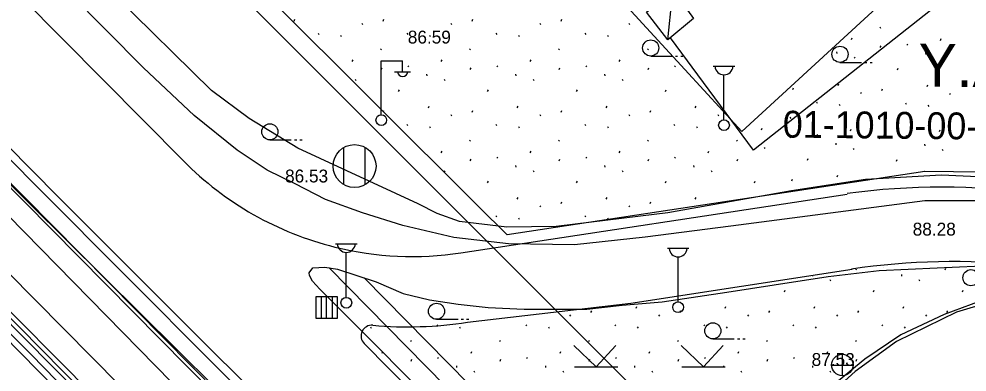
# Model space of a CAD drawing. Extents: x 412225 to 413380, y 4456471 to 4457189.
# Drawn here: x 412532.8 to 412621.2, y 4456847.1 to 4456880 of the extents above; entities that cross this region are included whole.
import ezdxf

# ---------------------------------------------------------------- set-up
doc = ezdxf.new("R2010")
doc.units = 0
for name, color, linetype in [('0_HALİHAZIR', 7, 'Continuous'), ('0_KADASTRO', 7, 'Continuous'), ('Level 27', 7, 'Continuous'), ('Level 28', 7, 'Continuous'), ('Level 41', 7, 'Continuous'), ('Level 56', 7, 'Continuous'), ('Level 57', 7, 'Continuous'), ('Level 62', 7, 'Continuous'), ('Level 8', 7, 'Continuous')]:
    doc.layers.add(name, color=color, linetype=linetype)

msp = doc.modelspace()

# ---------------------------------------------------------------- linework, layer by layer
at = {"layer": '0_HALİHAZIR'}
for p, q in [((412593.314, 4456878.021), (412593.767, 4456882.742)), ((412566.588, 4456871.077), (412566.588, 4456876.077)), ((412566.588, 4456876.077), (412568.588, 4456876.077)), ((412568.588, 4456875.077), (412568.588, 4456876.077)), ((412591.707, 4456876.524), (412593.707, 4456876.524)), ((412594.007, 4456876.524), (412594.207, 4456876.524)), ((412594.507, 4456876.524), (412594.707, 4456876.524)), ((412609.348, 4456875.935), (412611.348, 4456875.934)), ((412611.648, 4456875.934), (412611.848, 4456875.934)), ((412612.148, 4456875.934), (412612.348, 4456875.934)), ((412567.828, 4456875.037), (412569.328, 4456875.037)), ((412597.537, 4456875.58), (412599.537, 4456875.58)), ((412598.537, 4456870.58), (412598.537, 4456874.773)), ((412556.214, 4456868.712), (412558.214, 4456868.712)), ((412558.514, 4456868.712), (412558.714, 4456868.712)), ((412559.014, 4456868.712), (412559.214, 4456868.712)), ((412563.107, 4456864.536), (412563.107, 4456867.996)), ((412565.107, 4456864.536), (412565.107, 4456867.996)), ((412562.339, 4456859.028), (412564.339, 4456859.028)), ((412593.262, 4456858.61), (412595.262, 4456858.61)), ((412563.339, 4456854.028), (412563.339, 4456858.221)), ((412594.262, 4456853.61), (412594.262, 4456857.803)), ((412562.506, 4456854.084), (412560.506, 4456854.084)), ((412560.506, 4456854.084), (412560.506, 4456852.084)), ((412562.506, 4456854.084), (412560.506, 4456854.084)), ((412560.506, 4456854.084), (412560.506, 4456852.084)), ((412561.011, 4456852.084), (412561.011, 4456854.084)), ((412561.506, 4456852.084), (412561.506, 4456854.084)), ((412562.054, 4456852.084), (412562.054, 4456854.084)), ((412562.506, 4456852.084), (412562.506, 4456854.084)), ((412562.506, 4456852.084), (412562.506, 4456854.084)), ((412560.506, 4456852.084), (412562.506, 4456852.084)), ((412560.506, 4456852.084), (412562.506, 4456852.084)), ((412571.748, 4456851.983), (412573.748, 4456851.983)), ((412574.048, 4456851.983), (412574.248, 4456851.983)), ((412574.548, 4456851.983), (412574.748, 4456851.983)), ((412586.614, 4456847.539), (412584.554, 4456849.529)), ((412586.614, 4456847.539), (412588.464, 4456849.549)), ((412596.614, 4456847.538), (412594.554, 4456849.529)), ((412596.614, 4456847.538), (412598.464, 4456849.548)), ((412597.498, 4456850.158), (412599.498, 4456850.158)), ((412599.798, 4456850.158), (412599.998, 4456850.158)), ((412600.298, 4456850.158), (412600.498, 4456850.158)), ((412609.578, 4456846.717), (412609.578, 4456848.717)), ((412608.558, 4456847.707), (412610.558, 4456847.707)), ((412584.594, 4456847.539), (412588.634, 4456847.539)), ((412594.594, 4456847.539), (412598.634, 4456847.538))]:
    msp.add_line(p, q, dxfattribs=at)
for points in [[(412644.931, 4456753.555), (412630.555, 4456767.782), (412604.684, 4456793.709), (412582.154, 4456816.287), (412559.135, 4456839.628), (412534.75, 4456864.124), (412499.888, 4456899.345), (412487.433, 4456911.736), (412459.99, 4456939.333), (412440.337, 4456959.115), (412419.902, 4456979.921), (412392.691, 4457007.039), (412362.588, 4457037.58), (412334.209, 4457066.321), (412297.701, 4457103.437), (412284.18, 4457117.149)], [(412284.17, 4457116.265), (412296.803, 4457102.771), (412316.426, 4457082.291), (412338.061, 4457060.18), (412363.233, 4457034.899), (412383.867, 4457014.022), (412425.083, 4456972.499), (412446.131, 4456951.075), (412463.226, 4456933.647), (412501.75, 4456894.857), (412523.558, 4456872.918), (412554.446, 4456842.344)], [(412283.985, 4457100.322), (412303.353, 4457080.961), (412332.911, 4457051.149), (412362.488, 4457021.336), (412400.253, 4456983.455), (412425.306, 4456957.949), (412451.956, 4456931.175), (412483.613, 4456899.459), (412507.045, 4456875.463), (412533.953, 4456848.693), (412570.746, 4456810.938), (412594.382, 4456786.967), (412618.72, 4456762.275), (412633.267, 4456747.178), (412636.335, 4456744.215)], [(412645.421, 4456754.062), (412629.127, 4456770.178), (412599.147, 4456800.409), (412567.615, 4456832.31), (412536.489, 4456863.396), (412502.72, 4456897.599), (412471.675, 4456928.735), (412445.148, 4456955.565), (412406.259, 4456994.837)], [(412637.165, 4456746.318), (412618.159, 4456765.78), (412589.798, 4456794.375), (412560.702, 4456823.748), (412525.834, 4456858.92), (412495.532, 4456889.87), (412469.975, 4456915.531), (412420.275, 4456965.756), (412393.731, 4456992.619)], [(412414.019, 4456980.608), (412430.818, 4456963.728), (412462.102, 4456931.987), (412481.52, 4456912.466), (412499.923, 4456893.817), (412530.253, 4456863.229), (412548.59, 4456844.546), (412567.492, 4456825.478), (412597.357, 4456795.212), (412619.629, 4456772.724)], [(412412.412, 4456976.824), (412430.58, 4456958.484), (412471.136, 4456917.576), (412494.611, 4456893.791), (412529.094, 4456859.09), (412552.718, 4456835.192), (412591.392, 4456796.015), (412615.481, 4456771.779), (412632.916, 4456754.119)], [(412635.095, 4456744.706), (412621.293, 4456758.968), (412594.514, 4456786.189), (412564.28, 4456816.959), (412527.989, 4456853.886), (412497.963, 4456883.985), (412468.818, 4456913.357), (412423.738, 4456958.933), (412408.728, 4456974.086)], [(412637.945, 4456899.275), (412621.744, 4456883.95), (412601.277, 4456867.764)], [(412635.655, 4456863.173), (412632.712, 4456864.33), (412628.216, 4456864.971), (412618.808, 4456865.408), (412611.713, 4456865.008), (412604.825, 4456863.97), (412593.317, 4456861.895), (412589.231, 4456861.424), (412582.882, 4456860.625), (412578.297, 4456860.557), (412573.901, 4456861.085), (412571.802, 4456861.843), (412570.047, 4456862.738), (412558.81, 4456867.948), (412554.283, 4456870.692), (412550.76, 4456873.32), (412541.737, 4456882.227), (412530.428, 4456894.636)], [(412623.327, 4456863.035), (412617.262, 4456863.012), (412609.896, 4456862.049), (412599.167, 4456860.676), (412591.194, 4456859.655), (412584.597, 4456858.934), (412578.465, 4456859.008), (412573.344, 4456859.624), (412568.611, 4456860.738), (412564.846, 4456861.915), (412561.409, 4456863.163), (412558.561, 4456864.601), (412555.978, 4456865.878), (412553.156, 4456867.743), (412549.147, 4456870.988), (412544.431, 4456875.423), (412537.507, 4456882.438), (412529.679, 4456890.558)], [(412601.277, 4456867.764), (412593.565, 4456878.231)], [(412574.046, 4456841.577), (412560.867, 4456854.796), (412560.182, 4456855.542), (412559.895, 4456856.064), (412559.891, 4456856.327), (412560.23, 4456856.792), (412561.346, 4456856.858), (412562.516, 4456856.661), (412566.117, 4456855.465), (412568.631, 4456854.384), (412571.105, 4456853.812), (412573.757, 4456853.407), (412576.556, 4456853.086), (412579.928, 4456852.939), (412582.936, 4456852.933), (412585.763, 4456852.942), (412589.045, 4456853.286), (412592.771, 4456853.603), (412598.79, 4456854.513), (412603.218, 4456855.186), (412608.253, 4456855.967), (412612.995, 4456856.546), (412618.415, 4456856.79), (412623.951, 4456857.035)], [(412597.174, 4456820.503), (412576.231, 4456842.04), (412561.741, 4456856.791)], [(412565.002, 4456855.835), (412578.684, 4456841.949), (412597.738, 4456822.746)], [(412652.353, 4456846.965), (412647.413, 4456849.769), (412643.247, 4456851.45), (412638.775, 4456852.65), (412633.482, 4456853.773), (412630.335, 4456854.302), (412627.786, 4456854.429), (412625.207, 4456854.276), (412622.405, 4456853.676), (412619.054, 4456852.427), (412615.022, 4456850.527), (412611.653, 4456848.275), (412608.162, 4456845.364)]]:
    msp.add_lwpolyline(points, dxfattribs=at)
msp.add_lwpolyline([(412593.314, 4456878.021), (412591.319, 4456880.602), (412593.767, 4456882.742), (412595.699, 4456880.014)], close=True, dxfattribs=at)
for centre, radius in [((412591.707, 4456877.274), 0.75), ((412609.348, 4456876.685), 0.75), ((412566.599, 4456870.552), 0.5), ((412556.214, 4456869.462), 0.75), ((412598.537, 4456870.08), 0.5), ((412564.107, 4456866.266), 2), ((412621.55, 4456855.861), 0.75), ((412563.339, 4456853.528), 0.5), ((412571.748, 4456852.733), 0.75), ((412594.262, 4456853.11), 0.5), ((412597.498, 4456850.908), 0.75), ((412609.563, 4456847.725), 1)]:
    msp.add_circle(centre, radius, dxfattribs=at)
for centre, radius, start, end in [((412568.588, 4456875.08), 0.474, 184.83843, 355.14641), ((412598.537, 4456875.61), 0.837, 183.298, 356.90719), ((412563.339, 4456859.058), 0.837, 183.298, 356.90719), ((412594.262, 4456858.64), 0.837, 183.298, 356.90719)]:
    msp.add_arc(centre, radius, start, end, dxfattribs=at)
at = {"layer": '0_KADASTRO'}
msp.add_lwpolyline([(412586.676, 4456884.209), (412587.381, 4456884.857), (412598.621, 4456895.193), (412622.008, 4456916.7), (412635.546, 4456901.978), (412618.448, 4456886.255), (412600.214, 4456869.487), (412594.888, 4456875.278)], close=True, dxfattribs=at)
at = {"layer": 'Level 27'}
for p, q in [((412575.673, 4456862.499), (412536.456, 4456901.576)), ((412578.33, 4456859.851), (412575.673, 4456862.499))]:
    msp.add_line(p, q, dxfattribs=at)
at = {"layer": 'Level 28'}
msp.add_line((412617.243, 4456865.774), (412578.33, 4456859.851), dxfattribs=at)
msp.add_lwpolyline([(412632.353, 4456864.457), (412625.372, 4456865.654), (412617.213, 4456865.769)], dxfattribs=at)
at = {"layer": 'Level 41'}
for p, q in [((412558.48, 4456879.788), (412558.551, 4456879.948)), ((412564.785, 4456879.58), (412564.856, 4456879.474)), ((412566.773, 4456879.788), (412566.844, 4456879.948)), ((412573.078, 4456879.58), (412573.149, 4456879.474)), ((412575.066, 4456879.788), (412575.137, 4456879.948)), ((412581.371, 4456879.58), (412581.442, 4456879.474)), ((412583.359, 4456879.788), (412583.43, 4456879.948)), ((412589.664, 4456879.58), (412589.735, 4456879.474)), ((412560.7, 4456878.651), (412560.771, 4456878.544)), ((412568.993, 4456878.651), (412569.064, 4456878.544)), ((412577.286, 4456878.651), (412577.357, 4456878.544)), ((412585.579, 4456878.651), (412585.65, 4456878.544)), ((412613.068, 4456879.238), (412613.138, 4456879.13)), ((412562.799, 4456878.459), (412562.87, 4456878.352)), ((412571.092, 4456878.459), (412571.163, 4456878.352)), ((412579.385, 4456878.459), (412579.456, 4456878.352)), ((412587.678, 4456878.459), (412587.749, 4456878.352)), ((412610.415, 4456878.072), (412610.488, 4456878.23)), ((412618.708, 4456877.987), (412618.78, 4456878.145)), ((412566.537, 4456877.198), (412566.608, 4456877.091)), ((412574.83, 4456877.198), (412574.901, 4456877.091)), ((412583.123, 4456877.198), (412583.194, 4456877.091)), ((412591.416, 4456877.198), (412591.487, 4456877.091)), ((412609.032, 4456876.911), (412609.048, 4456876.751)), ((412613.106, 4456877.315), (412613.18, 4456877.474)), ((412615.575, 4456877.635), (412615.645, 4456877.527)), ((412617.325, 4456876.826), (412617.341, 4456876.666)), ((412563.896, 4456876.005), (412563.967, 4456876.164)), ((412572.189, 4456876.005), (412572.26, 4456876.164)), ((412580.482, 4456876.005), (412580.553, 4456876.164)), ((412588.775, 4456876.005), (412588.846, 4456876.164)), ((412610.657, 4456876.424), (412610.726, 4456876.316)), ((412618.95, 4456876.339), (412619.019, 4456876.232)), ((412566.595, 4456875.276), (412566.667, 4456875.436)), ((412569.06, 4456875.621), (412569.131, 4456875.514)), ((412574.888, 4456875.276), (412574.96, 4456875.436)), ((412577.353, 4456875.621), (412577.424, 4456875.514)), ((412583.181, 4456875.276), (412583.253, 4456875.436)), ((412585.646, 4456875.621), (412585.717, 4456875.514)), ((412591.474, 4456875.276), (412591.546, 4456875.436)), ((412593.939, 4456875.621), (412594.01, 4456875.514)), ((412614.701, 4456875.239), (412614.775, 4456875.398)), ((412564.155, 4456874.36), (412564.225, 4456874.253)), ((412570.818, 4456874.83), (412570.836, 4456874.67)), ((412572.448, 4456874.36), (412572.518, 4456874.253)), ((412579.111, 4456874.83), (412579.129, 4456874.67)), ((412580.741, 4456874.36), (412580.811, 4456874.253)), ((412587.404, 4456874.83), (412587.422, 4456874.67)), ((412589.034, 4456874.36), (412589.104, 4456874.253)), ((412568.211, 4456873.216), (412568.283, 4456873.376)), ((412576.504, 4456873.216), (412576.576, 4456873.376)), ((412584.797, 4456873.216), (412584.869, 4456873.376)), ((412593.09, 4456873.216), (412593.162, 4456873.376)), ((412604.951, 4456873.4), (412605.024, 4456873.56)), ((412609.165, 4456873.765), (412609.236, 4456873.925)), ((412613.243, 4456873.316), (412613.316, 4456873.475)), ((412617.457, 4456873.68), (412617.529, 4456873.84)), ((412611.253, 4456873.128), (412611.323, 4456873.021)), ((412619.546, 4456873.043), (412619.616, 4456872.936)), ((412570.983, 4456871.686), (412571.053, 4456871.846)), ((412579.276, 4456871.686), (412579.346, 4456871.846)), ((412587.569, 4456871.686), (412587.639, 4456871.846)), ((412595.862, 4456871.686), (412595.932, 4456871.846)), ((412607.159, 4456872.241), (412607.229, 4456872.133)), ((412609.256, 4456872.027), (412609.326, 4456871.92)), ((412615.452, 4456872.156), (412615.522, 4456872.048)), ((412617.549, 4456871.942), (412617.619, 4456871.835)), ((412566.8, 4456871.34), (412566.844, 4456871.438)), ((412573.078, 4456871.07), (412573.149, 4456870.964)), ((412575.066, 4456871.278), (412575.137, 4456871.438)), ((412581.371, 4456871.07), (412581.442, 4456870.964)), ((412583.359, 4456871.278), (412583.43, 4456871.438)), ((412589.664, 4456871.07), (412589.735, 4456870.964)), ((412591.652, 4456871.278), (412591.723, 4456871.438)), ((412597.957, 4456871.07), (412598.028, 4456870.964)), ((412604.688, 4456870.813), (412604.758, 4456870.705)), ((412612.981, 4456870.728), (412613.051, 4456870.62)), ((412568.993, 4456870.141), (412569.064, 4456870.034)), ((412571.092, 4456869.949), (412571.163, 4456869.842)), ((412577.286, 4456870.141), (412577.357, 4456870.034)), ((412579.385, 4456869.949), (412579.456, 4456869.842)), ((412585.579, 4456870.141), (412585.65, 4456870.034)), ((412587.678, 4456869.949), (412587.749, 4456869.842)), ((412593.872, 4456870.141), (412593.943, 4456870.034)), ((412595.971, 4456869.949), (412596.042, 4456869.842)), ((412602.035, 4456869.647), (412602.108, 4456869.805)), ((412610.328, 4456869.562), (412610.401, 4456869.72)), ((412604.727, 4456868.89), (412604.8, 4456869.05)), ((412607.195, 4456869.21), (412607.265, 4456869.102)), ((412613.019, 4456868.806), (412613.093, 4456868.965)), ((412615.488, 4456869.125), (412615.558, 4456869.018)), ((412618.62, 4456869.477), (412618.693, 4456869.636)), ((412574.83, 4456868.688), (412574.901, 4456868.581)), ((412583.123, 4456868.688), (412583.194, 4456868.581)), ((412591.416, 4456868.688), (412591.487, 4456868.581)), ((412599.709, 4456868.688), (412599.78, 4456868.581)), ((412602.277, 4456867.999), (412602.346, 4456867.892)), ((412608.945, 4456868.401), (412608.961, 4456868.241)), ((412617.237, 4456868.316), (412617.254, 4456868.156)), ((412572.189, 4456867.495), (412572.26, 4456867.654)), ((412577.353, 4456867.111), (412577.424, 4456867.004)), ((412580.482, 4456867.495), (412580.553, 4456867.654)), ((412585.646, 4456867.111), (412585.717, 4456867.004)), ((412588.775, 4456867.495), (412588.846, 4456867.654)), ((412593.939, 4456867.111), (412594.01, 4456867.004)), ((412597.068, 4456867.495), (412597.139, 4456867.654)), ((412610.57, 4456867.915), (412610.639, 4456867.807)), ((412618.863, 4456867.83), (412618.932, 4456867.722)), ((412574.888, 4456866.766), (412574.96, 4456866.926)), ((412579.111, 4456866.32), (412579.129, 4456866.16)), ((412583.181, 4456866.766), (412583.253, 4456866.926)), ((412587.404, 4456866.32), (412587.422, 4456866.16)), ((412591.474, 4456866.766), (412591.546, 4456866.926)), ((412595.697, 4456866.32), (412595.715, 4456866.16)), ((412599.767, 4456866.766), (412599.839, 4456866.926)), ((412606.322, 4456866.814), (412606.395, 4456866.973)), ((412614.614, 4456866.729), (412614.688, 4456866.888)), ((412572.448, 4456865.85), (412572.518, 4456865.743)), ((412580.741, 4456865.85), (412580.811, 4456865.743)), ((412589.034, 4456865.85), (412589.104, 4456865.743)), ((412597.327, 4456865.85), (412597.397, 4456865.743)), ((412609.078, 4456865.256), (412609.149, 4456865.415)), ((412576.504, 4456864.706), (412576.576, 4456864.866)), ((412584.797, 4456864.706), (412584.869, 4456864.866)), ((412593.09, 4456864.706), (412593.162, 4456864.866)), ((412601.383, 4456864.706), (412601.455, 4456864.866)), ((412604.864, 4456864.891), (412604.936, 4456865.05)), ((412579.276, 4456863.176), (412579.346, 4456863.336)), ((412583.359, 4456862.768), (412583.43, 4456862.928)), ((412587.569, 4456863.176), (412587.639, 4456863.336)), ((412591.652, 4456862.768), (412591.723, 4456862.928)), ((412595.862, 4456863.176), (412595.932, 4456863.336)), ((412581.371, 4456862.56), (412581.442, 4456862.454)), ((412589.664, 4456862.56), (412589.735, 4456862.454)), ((412577.286, 4456861.631), (412577.357, 4456861.524)), ((412579.385, 4456861.439), (412579.456, 4456861.332)), ((412585.579, 4456861.631), (412585.65, 4456861.524)), ((412587.678, 4456861.439), (412587.749, 4456861.332)), ((412610.842, 4456856.602), (412610.878, 4456856.683)), ((412613.368, 4456856.854), (412613.378, 4456856.84)), ((412619.135, 4456856.602), (412619.207, 4456856.762)), ((412606.779, 4456856.09), (412606.79, 4456855.996)), ((412608.402, 4456855.686), (412608.472, 4456855.579)), ((412615.065, 4456856.156), (412615.083, 4456855.996)), ((412616.695, 4456855.686), (412616.765, 4456855.579)), ((412604.165, 4456854.542), (412604.237, 4456854.702)), ((412612.458, 4456854.542), (412612.53, 4456854.702)), ((412620.751, 4456854.542), (412620.823, 4456854.702)), ((412590.351, 4456853.012), (412590.421, 4456853.172)), ((412598.644, 4456853.012), (412598.714, 4456853.172)), ((412606.937, 4456853.012), (412607.007, 4456853.172)), ((412615.23, 4456853.012), (412615.3, 4456853.172)), ((412584.153, 4456852.396), (412584.224, 4456852.29)), ((412586.141, 4456852.604), (412586.212, 4456852.764)), ((412592.446, 4456852.396), (412592.517, 4456852.29)), ((412594.434, 4456852.604), (412594.505, 4456852.764)), ((412600.739, 4456852.396), (412600.81, 4456852.29)), ((412602.727, 4456852.604), (412602.798, 4456852.764)), ((412609.032, 4456852.396), (412609.103, 4456852.29)), ((412611.02, 4456852.604), (412611.091, 4456852.764)), ((412617.325, 4456852.396), (412617.396, 4456852.29)), ((412619.313, 4456852.604), (412619.384, 4456852.764)), ((412565.581, 4456851.275), (412565.652, 4456851.168)), ((412571.775, 4456851.467), (412571.846, 4456851.36)), ((412573.874, 4456851.275), (412573.945, 4456851.168)), ((412580.068, 4456851.467), (412580.139, 4456851.36)), ((412582.167, 4456851.275), (412582.238, 4456851.168)), ((412588.361, 4456851.467), (412588.432, 4456851.36)), ((412590.46, 4456851.275), (412590.531, 4456851.168)), ((412596.654, 4456851.467), (412596.725, 4456851.36)), ((412598.753, 4456851.275), (412598.824, 4456851.168)), ((412604.947, 4456851.467), (412605.018, 4456851.36)), ((412607.046, 4456851.275), (412607.117, 4456851.168)), ((412613.24, 4456851.467), (412613.311, 4456851.36)), ((412615.339, 4456851.275), (412615.41, 4456851.168)), ((412569.319, 4456850.014), (412569.39, 4456849.907)), ((412577.612, 4456850.014), (412577.683, 4456849.907)), ((412585.905, 4456850.014), (412585.976, 4456849.907)), ((412594.198, 4456850.014), (412594.269, 4456849.907)), ((412602.491, 4456850.014), (412602.562, 4456849.907)), ((412610.784, 4456850.014), (412610.855, 4456849.907)), ((412566.678, 4456848.821), (412566.749, 4456848.98)), ((412574.971, 4456848.821), (412575.042, 4456848.98)), ((412583.264, 4456848.821), (412583.335, 4456848.98)), ((412591.557, 4456848.821), (412591.628, 4456848.98)), ((412599.85, 4456848.821), (412599.921, 4456848.98)), ((412608.143, 4456848.821), (412608.214, 4456848.98)), ((412569.377, 4456848.092), (412569.449, 4456848.252)), ((412571.842, 4456848.437), (412571.913, 4456848.33)), ((412573.6, 4456847.646), (412573.618, 4456847.486)), ((412577.67, 4456848.092), (412577.742, 4456848.252)), ((412580.135, 4456848.437), (412580.206, 4456848.33)), ((412581.893, 4456847.646), (412581.911, 4456847.486)), ((412585.963, 4456848.092), (412586.035, 4456848.252)), ((412588.428, 4456848.437), (412588.499, 4456848.33)), ((412590.186, 4456847.646), (412590.204, 4456847.486)), ((412594.256, 4456848.092), (412594.328, 4456848.252)), ((412596.721, 4456848.437), (412596.792, 4456848.33)), ((412598.479, 4456847.646), (412598.497, 4456847.486)), ((412602.549, 4456848.092), (412602.621, 4456848.252)), ((412605.014, 4456848.437), (412605.085, 4456848.33)), ((412606.772, 4456847.646), (412606.79, 4456847.486)), ((412610.842, 4456848.092), (412610.914, 4456848.252)), ((412575.23, 4456847.176), (412575.3, 4456847.069)), ((412583.523, 4456847.176), (412583.593, 4456847.069)), ((412591.816, 4456847.176), (412591.886, 4456847.069)), ((412600.109, 4456847.176), (412600.179, 4456847.069)), ((412608.402, 4456847.176), (412608.472, 4456847.069))]:
    msp.add_line(p, q, dxfattribs=at)
at = {"layer": 'Level 57'}
for points in [[(412600.214, 4456869.487), (412618.448, 4456886.255), (412635.546, 4456901.978)], [(412586.676, 4456884.209), (412594.888, 4456875.278), (412600.214, 4456869.487)]]:
    msp.add_lwpolyline(points, dxfattribs=at)
at = {"layer": 'Level 62'}
for p, q in [((412497.295, 4456899.362), (412643.049, 4456752.063)), ((412643.265, 4456752.271), (412497.51, 4456899.572)), ((412517.28, 4456897.96), (412536.93, 4456878.1)), ((412490.887, 4456893.113), (412636.434, 4456746.08)), ((412491.172, 4456893.395), (412636.692, 4456746.295)), ((412536.93, 4456878.1), (412548.169, 4456866.742)), ((412574.011, 4456858.182), (412610.011, 4456863.661)), ((412589.863, 4456853.484), (412610.493, 4456856.651)), ((412574.629, 4456851.701), (412589.863, 4456853.484)), ((412623.984, 4456853.782), (412620.195, 4456852.655)), ((412620.195, 4456852.655), (412614.6, 4456849.904)), ((412565.004, 4456849.724), (412594.825, 4456819.58)), ((412614.6, 4456849.904), (412610.751, 4456847.116)), ((412610.751, 4456847.116), (412605.356, 4456842.229))]:
    msp.add_line(p, q, dxfattribs=at)
for points in [[(412414.019, 4456980.608), (412430.818, 4456963.728), (412462.102, 4456931.987), (412481.52, 4456912.466), (412499.923, 4456893.817), (412530.253, 4456863.229), (412548.59, 4456844.546), (412567.492, 4456825.478), (412597.357, 4456795.212), (412619.629, 4456772.724)], [(412412.412, 4456976.824), (412430.58, 4456958.484), (412471.136, 4456917.576), (412494.611, 4456893.791), (412529.094, 4456859.09), (412552.718, 4456835.192), (412591.392, 4456796.015), (412615.481, 4456771.779), (412632.916, 4456754.119)]]:
    msp.add_lwpolyline(points, dxfattribs=at)
for centre, radius, start, end in [((412569.496, 4456887.84), 30, 224.69131, 256.07995), ((412618.899, 4456797.1), 67.202, 67.33879, 97.60635), ((412569.496, 4456887.84), 30, 256.07995, 278.65501), ((412619.746, 4456795.863), 61.5, 68.45902, 98.72658), ((412565.715, 4456850.427), 1, 84.94793, 224.69131), ((412569.061, 4456888.28), 37, 264.94792, 278.65501)]:
    msp.add_arc(centre, radius, start, end, dxfattribs=at)
at = {"layer": 'Level 8'}
msp.add_lwpolyline([(412706.1, 4457175.965), (412751.217, 4457041.463), (412764.575, 4457001.385), (412790.361, 4457003.87), (412821.118, 4456953.851), (412699.954, 4456860.338), (412631.485, 4456804.219), (412585.777, 4456849.927), (412523.439, 4456912.266), (412460.309, 4456974.831), (412403.512, 4457031.625), (412342.192, 4457092.946), (412287.774, 4457146.913), (412253.259, 4457181.199)], dxfattribs=at)

# ---------------------------------------------------------------- texts
at = {"layer": '0_HALİHAZIR'}
for s, p in [('86.59', (412569.068, 4456877.69)), ('86.53', (412557.63, 4456864.74)), ('88.28', (412616.124, 4456859.788)), ('87.53', (412606.708, 4456847.638))]:
    msp.add_text(s, height=1.2, dxfattribs=at).set_placement(p)
at = {"layer": 'Level 41'}
msp.add_text('Y.A.', height=4, rotation=359.4136, dxfattribs=at).set_placement((412616.635, 4456873.688))
at = {"layer": 'Level 56'}
msp.add_text('01-1010-00-028/5', height=2.5, rotation=359.4136, dxfattribs=at).set_placement((412604.008, 4456868.929))

doc.saveas('drawing.dxf')
